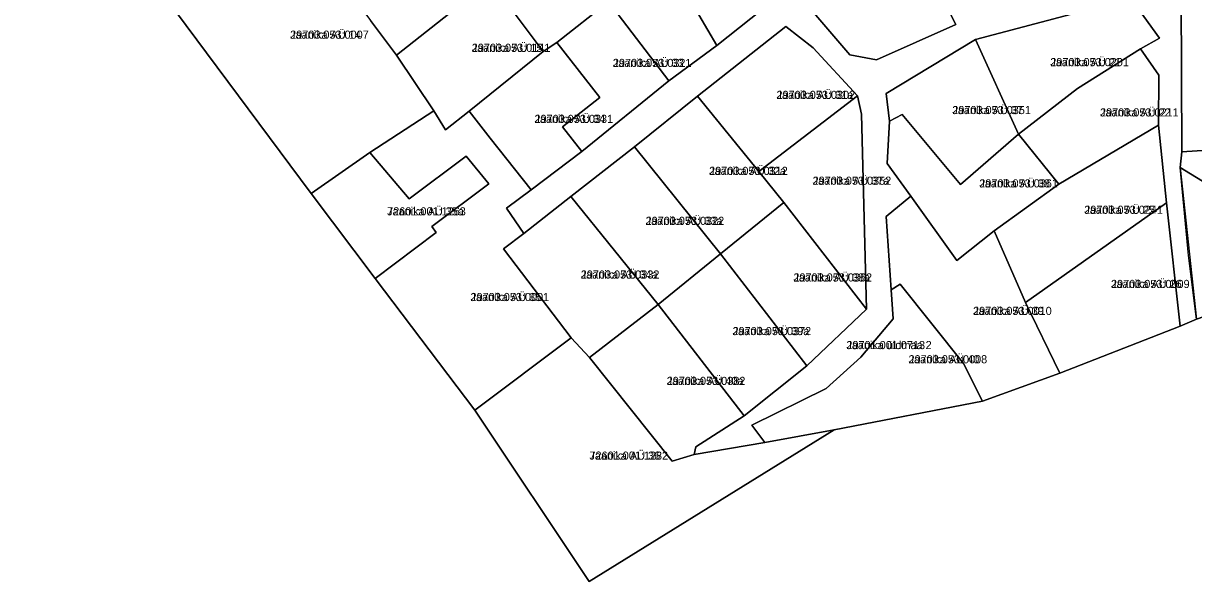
# Model space of a CAD drawing. Extents: x 504287 to 537970, y 6539941 to 6586214.
# Drawn here: x 519918.3 to 520134.2, y 6560331.5 to 6560434.4 of the extents above; entities that cross this region are included whole.
import ezdxf

# ---------------------------------------------------------------- set-up
doc = ezdxf.new("R2010")
doc.units = 0
for name, color, linetype in [('L_AADRESS', 7, 'Continuous'), ('PIIR', 7, 'Continuous'), ('TUNNUS', 7, 'Continuous')]:
    doc.layers.add(name, color=color, linetype=linetype)

msp = doc.modelspace()

# ---------------------------------------------------------------- linework, layer by layer
at = {"layer": 'PIIR'}
for points in [[(519883.63, 6560513.22), (519926.01, 6560463.67), (519941.07, 6560442.67), (519946.42, 6560436.64), (519971.42, 6560403.04), (519983.27, 6560387.35), (520001.63, 6560363.05), (520022.7, 6560331.46), (520067.9, 6560359.45), (520095.31, 6560364.72), (520109.58, 6560369.9), (520131.77, 6560378.57), (520134.78, 6560379.84), (520150.44, 6560385.26), (520172.45, 6560393.42), (520174.51, 6560395.38), (520176.91, 6560397.82), (520204.12, 6560404.43), (520229.4, 6560410.43), (520236.03, 6560412.01), (520261.34, 6560407.08), (520317.67, 6560410.76)], [(520131.93, 6560439.39), (520132.09, 6560410.71), (520131.78, 6560407.84), (520134.78, 6560379.84), (520131.77, 6560378.57), (520129.25, 6560401.31), (520127.79, 6560415.6), (520127.84, 6560424.83), (520124.41, 6560429.7), (520127.93, 6560431.67), (520122.64, 6560439.04), (520094, 6560431.4), (520077.51, 6560421.47), (520078.12, 6560416.36), (520077.71, 6560408.54), (520082.04, 6560402.56), (520077.54, 6560398.81), (520078.47, 6560385.24), (520078.84, 6560379.94), (520072.84, 6560372.86), (520066.42, 6560367.07), (520052.72, 6560360.32), (520055.12, 6560357.11), (520042.09, 6560354.91), (520042.43, 6560356.31), (520051.31, 6560362.01), (520062.9, 6560371.24), (520073.87, 6560381.71), (520072.97, 6560417.64), (520072.21, 6560421.07), (520064.03, 6560429.87), (520059, 6560433.83), (520042.72, 6560421), (520031.06, 6560411.66), (520019.32, 6560402.49), (520010.7, 6560395.66), (520007.47, 6560400.3), (520012.01, 6560403.72), (520021.39, 6560410.75), (520037.45, 6560423.8), (520046.27, 6560430.34), (520061.2, 6560442.26)], [(520063.43, 6560437.21), (520070.8, 6560428.59), (520075.72, 6560427.67), (520090.36, 6560434.21), (520085.67, 6560443.4)], [(519999.12, 6560437.93), (519987.16, 6560428.53), (519982.39, 6560434.96)]]:
    msp.add_lwpolyline(points, dxfattribs=at)
for points in [[(519941.07, 6560442.67), (519962.8, 6560460.63), (519968.04, 6560454.33), (519982.39, 6560434.96), (519987.16, 6560428.53), (519994.05, 6560418.29), (519982.28, 6560410.62), (519971.42, 6560403.04), (519946.42, 6560436.64)], [(520003.53, 6560443.51), (520020.45, 6560457.34), (520032.09, 6560443.2), (520026.3, 6560438.37), (520016.74, 6560430.9), (520014.25, 6560429.19)], [(520042.95, 6560435.96), (520048.18, 6560440.11), (520041.01, 6560450.19), (520049.34, 6560457.45), (520061.2, 6560442.26), (520046.27, 6560430.34)], [(520070.8, 6560428.59), (520063.43, 6560437.21), (520062.76, 6560442.07), (520077.42, 6560453.55), (520085.67, 6560443.4), (520090.36, 6560434.21), (520075.72, 6560427.67)], [(520032.09, 6560443.2), (520041.01, 6560450.19), (520048.18, 6560440.11), (520042.95, 6560435.96), (520046.27, 6560430.34), (520037.45, 6560423.8), (520026.3, 6560438.37)], [(519994.05, 6560418.29), (519987.16, 6560428.53), (519999.12, 6560437.93), (520003.53, 6560443.51), (520014.25, 6560429.19), (520000.56, 6560418.22), (519996.24, 6560414.79)], [(520131.93, 6560439.39), (520134.29, 6560440.71), (520148.02, 6560423.02), (520154.81, 6560414.22), (520148.08, 6560411.78), (520132.09, 6560410.71)], [(520026.3, 6560438.37), (520037.45, 6560423.8), (520021.39, 6560410.75), (520017.82, 6560415.32), (520024.71, 6560420.73), (520016.74, 6560430.9)], [(520122.64, 6560439.04), (520127.93, 6560431.67), (520124.41, 6560429.7), (520112.82, 6560422.37), (520101.93, 6560413.99), (520094, 6560431.4)], [(520064.03, 6560429.87), (520072.21, 6560421.07), (520054.02, 6560407.11), (520042.72, 6560421), (520059, 6560433.83)], [(520000.56, 6560418.22), (520014.25, 6560429.19), (520016.74, 6560430.9), (520024.71, 6560420.73), (520017.82, 6560415.32), (520021.39, 6560410.75), (520012.01, 6560403.72), (520004.46, 6560413.25)], [(520078.12, 6560416.36), (520077.51, 6560421.47), (520094, 6560431.4), (520101.93, 6560413.99), (520091.26, 6560404.67), (520080.46, 6560417.59)], [(520101.93, 6560413.99), (520112.82, 6560422.37), (520124.41, 6560429.7), (520127.84, 6560424.83), (520127.79, 6560415.6), (520109.39, 6560404.78)], [(520042.72, 6560421), (520054.02, 6560407.11), (520058.66, 6560401.39), (520046.95, 6560391.93), (520031.06, 6560411.66)], [(520054.02, 6560407.11), (520072.21, 6560421.07), (520072.97, 6560417.64), (520073.87, 6560381.71), (520058.66, 6560401.39)], [(519983.27, 6560387.35), (519994.51, 6560395.83), (519993.7, 6560396.94), (520004.2, 6560404.81), (520000.04, 6560409.91), (519989.53, 6560402.03), (519982.28, 6560410.62), (519994.05, 6560418.29), (519996.24, 6560414.79), (520000.56, 6560418.22), (520004.46, 6560413.25), (520012.01, 6560403.72), (520007.47, 6560400.3), (520010.7, 6560395.66), (520006.91, 6560392.8), (520019.41, 6560376.41), (520001.63, 6560363.05)], [(520082.04, 6560402.56), (520077.71, 6560408.54), (520078.12, 6560416.36), (520080.46, 6560417.59), (520091.26, 6560404.67), (520101.93, 6560413.99), (520109.39, 6560404.78), (520097.45, 6560396.16), (520090.53, 6560390.7)], [(520097.45, 6560396.16), (520109.39, 6560404.78), (520127.79, 6560415.6), (520129.25, 6560401.31), (520103.25, 6560382.95)], [(520147.48, 6560391.5), (520145.84, 6560390.81), (520139.7, 6560402.97), (520131.78, 6560407.84), (520132.09, 6560410.71), (520148.08, 6560411.78), (520154.81, 6560414.22), (520163.23, 6560402.74), (520166.04, 6560399.91), (520168.25, 6560402.09), (520174.65, 6560395.64), (520172.45, 6560393.46), (520150.39, 6560385.33)], [(520031.06, 6560411.66), (520046.95, 6560391.93), (520035.45, 6560382.53), (520019.32, 6560402.49)], [(519982.28, 6560410.62), (519989.53, 6560402.03), (520000.04, 6560409.91), (520004.2, 6560404.81), (519993.7, 6560396.94), (519994.51, 6560395.83), (519983.27, 6560387.35), (519971.42, 6560403.04)], [(520133.32, 6560391.61), (520131.78, 6560407.84), (520139.7, 6560402.97), (520145.84, 6560390.81), (520147.48, 6560391.5), (520150.39, 6560385.33), (520134.78, 6560379.84)], [(520006.91, 6560392.8), (520010.7, 6560395.66), (520019.32, 6560402.49), (520035.45, 6560382.53), (520022.76, 6560372.78), (520019.41, 6560376.41)], [(520077.54, 6560398.81), (520082.04, 6560402.56), (520090.53, 6560390.7), (520097.45, 6560396.16), (520103.25, 6560382.95), (520109.58, 6560369.9), (520095.31, 6560364.72), (520091.78, 6560371.66), (520080.09, 6560386.31), (520078.47, 6560385.24)], [(520058.66, 6560401.39), (520073.87, 6560381.71), (520062.9, 6560371.24), (520046.95, 6560391.93)], [(520103.25, 6560382.95), (520129.25, 6560401.31), (520131.77, 6560378.57), (520109.58, 6560369.9)], [(520046.95, 6560391.93), (520062.9, 6560371.24), (520051.31, 6560362.01), (520035.45, 6560382.53)], [(520052.72, 6560360.32), (520066.42, 6560367.07), (520072.84, 6560372.86), (520078.84, 6560379.94), (520078.47, 6560385.24), (520080.09, 6560386.31), (520091.78, 6560371.66), (520095.31, 6560364.72), (520067.9, 6560359.45), (520055.12, 6560357.11)], [(520035.45, 6560382.53), (520051.31, 6560362.01), (520042.43, 6560356.31), (520042.09, 6560354.91), (520038.05, 6560353.69), (520022.76, 6560372.78)], [(520022.76, 6560372.78), (520038.05, 6560353.69), (520042.09, 6560354.91), (520055.12, 6560357.11), (520067.9, 6560359.45), (520022.7, 6560331.46), (520001.63, 6560363.05), (520019.41, 6560376.41)]]:
    msp.add_lwpolyline(points, close=True, dxfattribs=at)

# ---------------------------------------------------------------- texts
at = {"layer": 'L_AADRESS'}
for s, p in [('Jaanika AÜ 14', (519967.56, 6560431.57)), ('Jaanika AÜ 15', (520001.07, 6560429.15)), ('Jaanika AÜ 33', (520027.1, 6560426.36)), ('Jaanika AÜ 21', (520107.8, 6560426.51)), ('Jaanika AÜ 31a', (520057.29, 6560420.47)), ('Jaanika AÜ 34', (520012.64, 6560416.04)), ('Jaanika AÜ 37', (520089.72, 6560417.67)), ('Jaanika AÜ 22', (520116.98, 6560417.24)), ('Jaanika AÜ 32a', (520044.86, 6560406.45)), ('Jaanika AÜ 37a', (520063.95, 6560404.64)), ('Jaanika AÜ 38', (520094.7, 6560404.15)), ('Jaanika AÜ 35a', (519985.46, 6560398.99)), ('Jaanika AÜ 25', (520114.07, 6560399.28)), ('Jaanika AÜ 33a', (520033.14, 6560397.24)), ('Jaanika AÜ 34a', (520021.18, 6560387.34)), ('Jaanika AÜ 38a', (520060.41, 6560386.8)), ('Jaanika AÜ 26', (520119, 6560385.6)), ('Jaanika AÜ 35', (520000.84, 6560383.19)), ('Jaanika AÜ 39', (520093.56, 6560380.63)), ('Jaanika AÜ 39a', (520049.18, 6560376.91)), ('Jaanika üldmaa 2', (520070.19, 6560374.33)), ('Jaanika AÜ 40', (520081.65, 6560371.71)), ('Jaanika AÜ 40a', (520037.04, 6560367.72)), ('Jaanika AÜ 36', (520022.78, 6560353.94))]:
    msp.add_text(s, height=1.5, dxfattribs=at).set_placement(p)
at = {"layer": 'TUNNUS'}
for s, p in [('29703:053:0007', (519967.56, 6560431.57)), ('29703:053:0141', (520001.07, 6560429.15)), ('29703:053:0321', (520027.1, 6560426.36)), ('29703:053:0201', (520107.8, 6560426.51)), ('29703:053:0302', (520057.29, 6560420.47)), ('29703:053:0351', (520089.72, 6560417.67)), ('29703:053:0211', (520116.98, 6560417.24)), ('29703:053:0331', (520012.64, 6560416.04)), ('29703:053:0312', (520044.86, 6560406.45)), ('29703:053:0352', (520063.95, 6560404.64)), ('29703:053:0361', (520094.7, 6560404.15)), ('72601:001:1263', (519985.46, 6560398.99)), ('29703:053:0241', (520114.07, 6560399.28)), ('29703:053:0322', (520033.14, 6560397.24)), ('29703:053:0332', (520021.18, 6560387.34)), ('29703:053:0362', (520060.41, 6560386.8)), ('29703:053:0009', (520119, 6560385.6)), ('29703:053:0001', (520000.84, 6560383.19)), ('29703:053:0010', (520093.56, 6560380.63)), ('29703:053:0372', (520049.18, 6560376.91)), ('29701:001:0713', (520070.19, 6560374.33)), ('29703:053:0008', (520081.65, 6560371.71)), ('29703:053:0382', (520037.04, 6560367.72)), ('72601:001:1282', (520022.78, 6560353.94))]:
    msp.add_text(s, height=1.5, dxfattribs=at).set_placement(p)

doc.saveas('drawing.dxf')
